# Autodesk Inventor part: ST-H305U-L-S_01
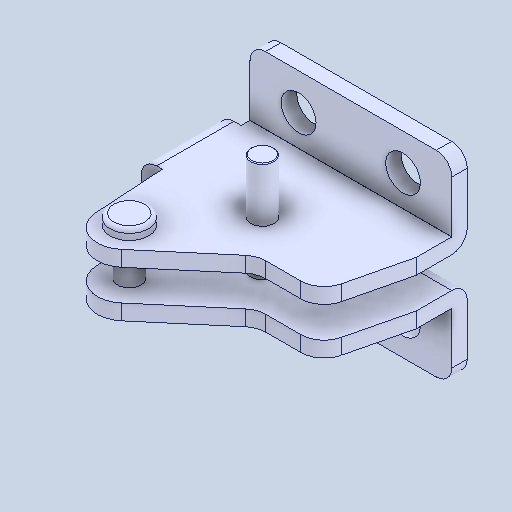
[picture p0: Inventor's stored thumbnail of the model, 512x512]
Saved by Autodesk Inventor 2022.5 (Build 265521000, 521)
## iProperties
Created: 2024-07
Part Number: ST-H305U-L-S_01
Material: 一般
Document SubType Name: Modeling
Designer: ImaoCorp
Density: 1 g/cm^3
Appearance: 既定
Author: ImaoCorp
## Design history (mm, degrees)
feature "ST-H305U-L-S_01"
node "ソリッド1"
